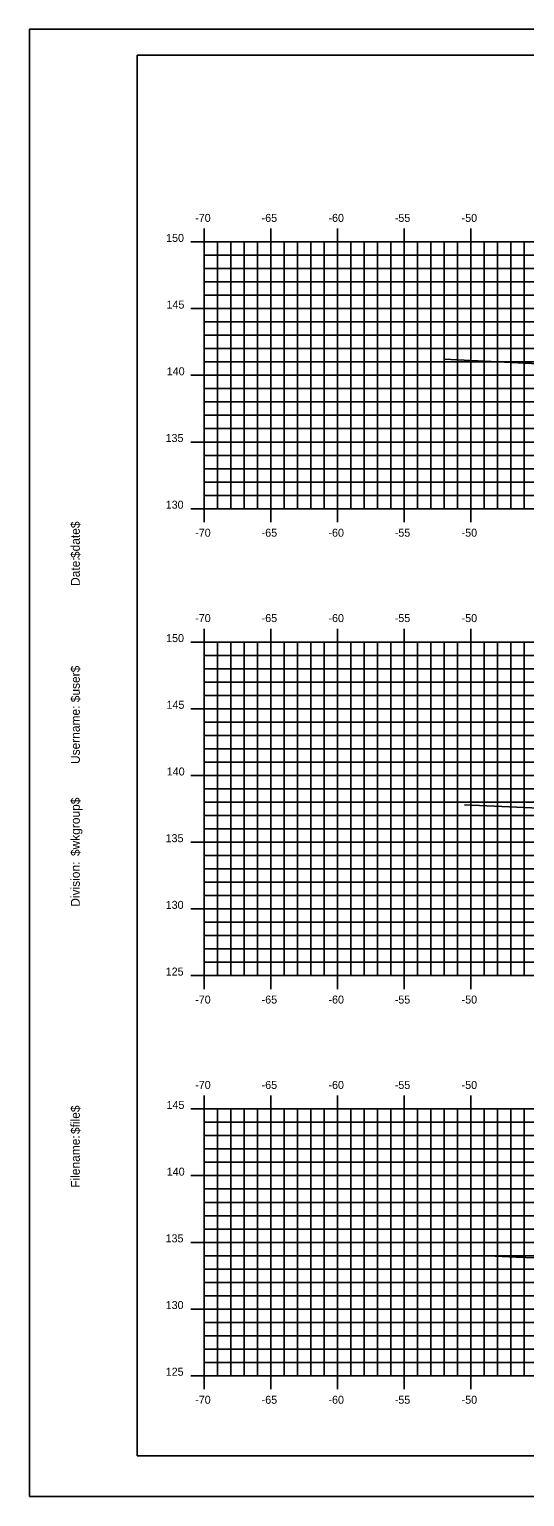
# Model space of a CAD drawing. Extents: x 1146525 to 1146695, y 608981 to 609091.
# Drawn here: x 1146524.6 to 1146561.7, y 608981.3 to 609091.3 of the extents above; entities that cross this region are included whole.
import ezdxf

# ---------------------------------------------------------------- set-up
doc = ezdxf.new("R2010")
doc.units = 0
for name, color, linetype in [('BORDER', 7, 'Continuous'), ('H_V ANNOTATION', 7, 'Continuous'), ('MAJOR', 7, 'Continuous'), ('MINOR', 7, 'Continuous'), ('PLOT BOUNDARY', 7, 'Continuous'), ('S_Roadway_Centerline', 7, 'Continuous')]:
    doc.layers.add(name, color=color, linetype=linetype)

msp = doc.modelspace()

# ---------------------------------------------------------------- linework, layer by layer
at = {"layer": 'BORDER'}
msp.add_lwpolyline([(1146532.67, 608984.34), (1146692.67, 608984.34), (1146692.67, 609089.34), (1146532.67, 609089.34)], close=True, dxfattribs=at)
at = {"layer": 'MAJOR'}
for p, q in [((1146537.67, 609076.34), (1146537.67, 609075.34)), ((1146542.67, 609076.34), (1146542.67, 609075.34)), ((1146547.67, 609076.34), (1146547.67, 609075.34)), ((1146552.67, 609076.34), (1146552.67, 609075.34)), ((1146557.67, 609076.34), (1146557.67, 609075.34)), ((1146536.67, 609075.34), (1146537.67, 609075.34)), ((1146537.67, 609075.34), (1146677.67, 609075.34)), ((1146537.67, 609055.34), (1146537.67, 609075.34)), ((1146537.67, 609055.34), (1146537.67, 609075.34)), ((1146537.67, 609075.34), (1146677.67, 609075.34)), ((1146542.67, 609055.34), (1146542.67, 609075.34)), ((1146547.67, 609055.34), (1146547.67, 609075.34)), ((1146552.67, 609055.34), (1146552.67, 609075.34)), ((1146557.67, 609055.34), (1146557.67, 609075.34)), ((1146536.67, 609070.34), (1146537.67, 609070.34)), ((1146537.67, 609070.34), (1146677.67, 609070.34)), ((1146536.67, 609065.34), (1146537.67, 609065.34)), ((1146537.67, 609065.34), (1146677.67, 609065.34)), ((1146536.67, 609060.34), (1146537.67, 609060.34)), ((1146537.67, 609060.34), (1146677.67, 609060.34)), ((1146536.67, 609055.34), (1146537.67, 609055.34)), ((1146537.67, 609055.34), (1146677.67, 609055.34)), ((1146537.67, 609055.34), (1146677.67, 609055.34)), ((1146537.67, 609054.33), (1146537.67, 609055.34)), ((1146542.67, 609054.33), (1146542.67, 609055.34)), ((1146547.67, 609054.33), (1146547.67, 609055.34)), ((1146552.67, 609054.33), (1146552.67, 609055.34)), ((1146557.67, 609054.33), (1146557.67, 609055.34)), ((1146537.67, 609046.34), (1146537.67, 609045.34)), ((1146542.67, 609046.34), (1146542.67, 609045.34)), ((1146547.67, 609046.34), (1146547.67, 609045.34)), ((1146552.67, 609046.34), (1146552.67, 609045.34)), ((1146557.67, 609046.34), (1146557.67, 609045.34)), ((1146536.67, 609045.34), (1146537.67, 609045.34)), ((1146537.67, 609045.34), (1146677.67, 609045.34)), ((1146537.67, 609020.34), (1146537.67, 609045.34)), ((1146537.67, 609020.34), (1146537.67, 609045.34)), ((1146537.67, 609045.34), (1146677.67, 609045.34)), ((1146542.67, 609020.34), (1146542.67, 609045.34)), ((1146547.67, 609020.34), (1146547.67, 609045.34)), ((1146552.67, 609020.34), (1146552.67, 609045.34)), ((1146557.67, 609020.34), (1146557.67, 609045.34)), ((1146536.67, 609040.34), (1146537.67, 609040.34)), ((1146537.67, 609040.34), (1146677.67, 609040.34)), ((1146536.67, 609035.34), (1146537.67, 609035.34)), ((1146537.67, 609035.34), (1146677.67, 609035.34)), ((1146536.67, 609030.34), (1146537.67, 609030.34)), ((1146537.67, 609030.34), (1146677.67, 609030.34)), ((1146536.67, 609025.34), (1146537.67, 609025.34)), ((1146537.67, 609025.34), (1146677.67, 609025.34)), ((1146536.67, 609020.34), (1146537.67, 609020.34)), ((1146537.67, 609020.34), (1146677.67, 609020.34)), ((1146537.67, 609020.34), (1146677.67, 609020.34)), ((1146537.67, 609019.33), (1146537.67, 609020.34)), ((1146542.67, 609019.33), (1146542.67, 609020.34)), ((1146547.67, 609019.33), (1146547.67, 609020.34)), ((1146552.67, 609019.33), (1146552.67, 609020.34)), ((1146557.67, 609019.33), (1146557.67, 609020.34)), ((1146537.67, 609011.34), (1146537.67, 609010.34)), ((1146542.67, 609011.34), (1146542.67, 609010.34)), ((1146547.67, 609011.34), (1146547.67, 609010.34)), ((1146552.67, 609011.34), (1146552.67, 609010.34)), ((1146557.67, 609011.34), (1146557.67, 609010.34)), ((1146536.67, 609010.34), (1146537.67, 609010.34)), ((1146537.67, 609010.34), (1146677.67, 609010.34)), ((1146537.67, 608990.34), (1146537.67, 609010.34)), ((1146537.67, 608990.34), (1146537.67, 609010.34)), ((1146537.67, 609010.34), (1146677.67, 609010.34)), ((1146542.67, 608990.34), (1146542.67, 609010.34)), ((1146547.67, 608990.34), (1146547.67, 609010.34)), ((1146552.67, 608990.34), (1146552.67, 609010.34)), ((1146557.67, 608990.34), (1146557.67, 609010.34)), ((1146536.67, 609005.34), (1146537.67, 609005.34)), ((1146537.67, 609005.34), (1146677.67, 609005.34)), ((1146536.67, 609000.34), (1146537.67, 609000.34)), ((1146537.67, 609000.34), (1146677.67, 609000.34)), ((1146536.67, 608995.34), (1146537.67, 608995.34)), ((1146537.67, 608995.34), (1146677.67, 608995.34)), ((1146536.67, 608990.34), (1146537.67, 608990.34)), ((1146537.67, 608990.34), (1146677.67, 608990.34)), ((1146537.67, 608990.34), (1146677.67, 608990.34)), ((1146537.67, 608989.33), (1146537.67, 608990.34)), ((1146542.67, 608989.33), (1146542.67, 608990.34)), ((1146547.67, 608989.33), (1146547.67, 608990.34)), ((1146552.67, 608989.33), (1146552.67, 608990.34)), ((1146557.67, 608989.33), (1146557.67, 608990.34))]:
    msp.add_line(p, q, dxfattribs=at)
at = {"layer": 'MINOR'}
for p, q in [((1146538.67, 609055.34), (1146538.67, 609075.34)), ((1146539.67, 609055.34), (1146539.67, 609075.34)), ((1146540.67, 609055.34), (1146540.67, 609075.34)), ((1146541.67, 609055.34), (1146541.67, 609075.34)), ((1146543.67, 609055.34), (1146543.67, 609075.34)), ((1146544.67, 609055.34), (1146544.67, 609075.34)), ((1146545.67, 609055.34), (1146545.67, 609075.34)), ((1146546.67, 609055.34), (1146546.67, 609075.34)), ((1146548.67, 609055.34), (1146548.67, 609075.34)), ((1146549.67, 609055.34), (1146549.67, 609075.34)), ((1146550.67, 609055.34), (1146550.67, 609075.34)), ((1146551.67, 609055.34), (1146551.67, 609075.34)), ((1146553.67, 609055.34), (1146553.67, 609075.34)), ((1146554.67, 609055.34), (1146554.67, 609075.34)), ((1146555.67, 609055.34), (1146555.67, 609075.34)), ((1146556.67, 609055.34), (1146556.67, 609075.34)), ((1146558.67, 609055.34), (1146558.67, 609075.34)), ((1146559.67, 609055.34), (1146559.67, 609075.34)), ((1146560.67, 609055.34), (1146560.67, 609075.34)), ((1146561.67, 609055.34), (1146561.67, 609075.34)), ((1146537.67, 609074.34), (1146677.67, 609074.34)), ((1146537.67, 609074.34), (1146538.67, 609074.34)), ((1146537.67, 609073.34), (1146677.67, 609073.34)), ((1146537.67, 609073.34), (1146538.67, 609073.34)), ((1146537.67, 609072.34), (1146677.67, 609072.34)), ((1146537.67, 609072.34), (1146538.67, 609072.34)), ((1146537.67, 609071.34), (1146677.67, 609071.34)), ((1146537.67, 609071.34), (1146538.67, 609071.34)), ((1146537.67, 609069.34), (1146677.67, 609069.34)), ((1146537.67, 609069.34), (1146538.67, 609069.34)), ((1146537.67, 609068.34), (1146677.67, 609068.34)), ((1146537.67, 609068.34), (1146538.67, 609068.34)), ((1146537.67, 609067.34), (1146677.67, 609067.34)), ((1146537.67, 609067.34), (1146538.67, 609067.34)), ((1146537.67, 609066.34), (1146677.67, 609066.34)), ((1146537.67, 609066.34), (1146538.67, 609066.34)), ((1146537.67, 609064.34), (1146677.67, 609064.34)), ((1146537.67, 609064.34), (1146538.67, 609064.34)), ((1146537.67, 609063.34), (1146677.67, 609063.34)), ((1146537.67, 609063.34), (1146538.67, 609063.34)), ((1146537.67, 609062.34), (1146677.67, 609062.34)), ((1146537.67, 609062.34), (1146538.67, 609062.34)), ((1146537.67, 609061.34), (1146677.67, 609061.34)), ((1146537.67, 609061.34), (1146538.67, 609061.34)), ((1146537.67, 609059.34), (1146677.67, 609059.34)), ((1146537.67, 609059.34), (1146538.67, 609059.34)), ((1146537.67, 609058.34), (1146677.67, 609058.34)), ((1146537.67, 609058.34), (1146538.67, 609058.34)), ((1146537.67, 609057.34), (1146677.67, 609057.34)), ((1146537.67, 609057.34), (1146538.67, 609057.34)), ((1146537.67, 609056.34), (1146677.67, 609056.34)), ((1146537.67, 609056.34), (1146538.67, 609056.34)), ((1146538.67, 609020.34), (1146538.67, 609045.34)), ((1146539.67, 609020.34), (1146539.67, 609045.34)), ((1146540.67, 609020.34), (1146540.67, 609045.34)), ((1146541.67, 609020.34), (1146541.67, 609045.34)), ((1146543.67, 609020.34), (1146543.67, 609045.34)), ((1146544.67, 609020.34), (1146544.67, 609045.34)), ((1146545.67, 609020.34), (1146545.67, 609045.34)), ((1146546.67, 609020.34), (1146546.67, 609045.34)), ((1146548.67, 609020.34), (1146548.67, 609045.34)), ((1146549.67, 609020.34), (1146549.67, 609045.34)), ((1146550.67, 609020.34), (1146550.67, 609045.34)), ((1146551.67, 609020.34), (1146551.67, 609045.34)), ((1146553.67, 609020.34), (1146553.67, 609045.34)), ((1146554.67, 609020.34), (1146554.67, 609045.34)), ((1146555.67, 609020.34), (1146555.67, 609045.34)), ((1146556.67, 609020.34), (1146556.67, 609045.34)), ((1146558.67, 609020.34), (1146558.67, 609045.34)), ((1146559.67, 609020.34), (1146559.67, 609045.34)), ((1146560.67, 609020.34), (1146560.67, 609045.34)), ((1146561.67, 609020.34), (1146561.67, 609045.34)), ((1146537.67, 609044.34), (1146677.67, 609044.34)), ((1146537.67, 609044.34), (1146538.67, 609044.34)), ((1146537.67, 609043.34), (1146677.67, 609043.34)), ((1146537.67, 609043.34), (1146538.67, 609043.34)), ((1146537.67, 609042.34), (1146677.67, 609042.34)), ((1146537.67, 609042.34), (1146538.67, 609042.34)), ((1146537.67, 609041.34), (1146677.67, 609041.34)), ((1146537.67, 609041.34), (1146538.67, 609041.34)), ((1146537.67, 609039.34), (1146677.67, 609039.34)), ((1146537.67, 609039.34), (1146538.67, 609039.34)), ((1146537.67, 609038.34), (1146677.67, 609038.34)), ((1146537.67, 609038.34), (1146538.67, 609038.34)), ((1146537.67, 609037.34), (1146677.67, 609037.34)), ((1146537.67, 609037.34), (1146538.67, 609037.34)), ((1146537.67, 609036.34), (1146677.67, 609036.34)), ((1146537.67, 609036.34), (1146538.67, 609036.34)), ((1146537.67, 609034.34), (1146677.67, 609034.34)), ((1146537.67, 609034.34), (1146538.67, 609034.34)), ((1146537.67, 609033.34), (1146677.67, 609033.34)), ((1146537.67, 609033.34), (1146538.67, 609033.34)), ((1146537.67, 609032.34), (1146677.67, 609032.34)), ((1146537.67, 609032.34), (1146538.67, 609032.34)), ((1146537.67, 609031.34), (1146677.67, 609031.34)), ((1146537.67, 609031.34), (1146538.67, 609031.34)), ((1146537.67, 609029.34), (1146677.67, 609029.34)), ((1146537.67, 609029.34), (1146538.67, 609029.34)), ((1146537.67, 609028.34), (1146677.67, 609028.34)), ((1146537.67, 609028.34), (1146538.67, 609028.34)), ((1146537.67, 609027.34), (1146677.67, 609027.34)), ((1146537.67, 609027.34), (1146538.67, 609027.34)), ((1146537.67, 609026.34), (1146677.67, 609026.34)), ((1146537.67, 609026.34), (1146538.67, 609026.34)), ((1146537.67, 609024.34), (1146677.67, 609024.34)), ((1146537.67, 609024.34), (1146538.67, 609024.34)), ((1146537.67, 609023.34), (1146677.67, 609023.34)), ((1146537.67, 609023.34), (1146538.67, 609023.34)), ((1146537.67, 609022.34), (1146677.67, 609022.34)), ((1146537.67, 609022.34), (1146538.67, 609022.34)), ((1146537.67, 609021.34), (1146677.67, 609021.34)), ((1146537.67, 609021.34), (1146538.67, 609021.34)), ((1146538.67, 608990.34), (1146538.67, 609010.34)), ((1146539.67, 608990.34), (1146539.67, 609010.34)), ((1146540.67, 608990.34), (1146540.67, 609010.34)), ((1146541.67, 608990.34), (1146541.67, 609010.34)), ((1146543.67, 608990.34), (1146543.67, 609010.34)), ((1146544.67, 608990.34), (1146544.67, 609010.34)), ((1146545.67, 608990.34), (1146545.67, 609010.34)), ((1146546.67, 608990.34), (1146546.67, 609010.34)), ((1146548.67, 608990.34), (1146548.67, 609010.34)), ((1146549.67, 608990.34), (1146549.67, 609010.34)), ((1146550.67, 608990.34), (1146550.67, 609010.34)), ((1146551.67, 608990.34), (1146551.67, 609010.34)), ((1146553.67, 608990.34), (1146553.67, 609010.34)), ((1146554.67, 608990.34), (1146554.67, 609010.34)), ((1146555.67, 608990.34), (1146555.67, 609010.34)), ((1146556.67, 608990.34), (1146556.67, 609010.34)), ((1146558.67, 608990.34), (1146558.67, 609010.34)), ((1146559.67, 608990.34), (1146559.67, 609010.34)), ((1146560.67, 608990.34), (1146560.67, 609010.34)), ((1146561.67, 608990.34), (1146561.67, 609010.34)), ((1146537.67, 609009.34), (1146677.67, 609009.34)), ((1146537.67, 609009.34), (1146538.67, 609009.34)), ((1146537.67, 609008.34), (1146677.67, 609008.34)), ((1146537.67, 609008.34), (1146538.67, 609008.34)), ((1146537.67, 609007.34), (1146677.67, 609007.34)), ((1146537.67, 609007.34), (1146538.67, 609007.34)), ((1146537.67, 609006.34), (1146677.67, 609006.34)), ((1146537.67, 609006.34), (1146538.67, 609006.34)), ((1146537.67, 609004.34), (1146677.67, 609004.34)), ((1146537.67, 609004.34), (1146538.67, 609004.34)), ((1146537.67, 609003.34), (1146677.67, 609003.34)), ((1146537.67, 609003.34), (1146538.67, 609003.34)), ((1146537.67, 609002.34), (1146677.67, 609002.34)), ((1146537.67, 609002.34), (1146538.67, 609002.34)), ((1146537.67, 609001.34), (1146677.67, 609001.34)), ((1146537.67, 609001.34), (1146538.67, 609001.34)), ((1146537.67, 608999.34), (1146677.67, 608999.34)), ((1146537.67, 608999.34), (1146538.67, 608999.34)), ((1146537.67, 608998.34), (1146677.67, 608998.34)), ((1146537.67, 608998.34), (1146538.67, 608998.34)), ((1146537.67, 608997.34), (1146677.67, 608997.34)), ((1146537.67, 608997.34), (1146538.67, 608997.34)), ((1146537.67, 608996.34), (1146677.67, 608996.34)), ((1146537.67, 608996.34), (1146538.67, 608996.34)), ((1146537.67, 608994.34), (1146677.67, 608994.34)), ((1146537.67, 608994.34), (1146538.67, 608994.34)), ((1146537.67, 608993.34), (1146677.67, 608993.34)), ((1146537.67, 608993.34), (1146538.67, 608993.34)), ((1146537.67, 608992.34), (1146677.67, 608992.34)), ((1146537.67, 608992.34), (1146538.67, 608992.34)), ((1146537.67, 608991.34), (1146677.67, 608991.34)), ((1146537.67, 608991.34), (1146538.67, 608991.34))]:
    msp.add_line(p, q, dxfattribs=at)
at = {"layer": 'PLOT BOUNDARY'}
msp.add_lwpolyline([(1146524.58, 608981.28), (1146694.58, 608981.28), (1146694.58, 609091.28), (1146524.58, 609091.28)], close=True, dxfattribs=at)
at = {"layer": 'S_Roadway_Centerline'}
for points in [[(1146555.66, 609066.54), (1146562.22, 609066.22), (1146582.41, 609065.07), (1146583.32, 609064.91), (1146587.85, 609063.5), (1146588.57, 609063.64), (1146593.36, 609064.95), (1146593.6, 609064.96), (1146595.56, 609064.97), (1146601.49, 609065.12), (1146606.93, 609065.19), (1146612.82, 609065.04), (1146617.66, 609064.93), (1146621.7, 609064.69), (1146621.82, 609064.68), (1146621.88, 609064.66), (1146624.76, 609063.49), (1146625.76, 609063.91), (1146635.49, 609067.85), (1146654.51, 609068.05), (1146655.61, 609068.02)], [(1146557.19, 609033.15), (1146565.05, 609032.78), (1146581.82, 609032.11), (1146584.31, 609031.66), (1146589.37, 609030.83), (1146592.03, 609031.48), (1146593.47, 609031.84), (1146594.03, 609031.88), (1146595.01, 609031.91), (1146600.28, 609032.09), (1146606.45, 609032.18), (1146612.28, 609032.04), (1146617.29, 609031.87), (1146619.52, 609031.64), (1146621.57, 609031.45), (1146622.76, 609030.93), (1146624.18, 609030.47), (1146629.55, 609032.75), (1146635.04, 609035.13), (1146648.1, 609035.72), (1146654.91, 609035.42)], [(1146558.97, 608999.32), (1146561.08, 608999.24), (1146581.4, 608998.53), (1146588.81, 608997.71), (1146588.86, 608997.7), (1146592.98, 608998.76), (1146592.99, 608998.76), (1146592.99, 608998.76), (1146594.91, 608998.76), (1146601.66, 608998.91), (1146606.09, 608999.07), (1146612.76, 608998.85), (1146617.1, 608998.7), (1146618.9, 608998.53), (1146621.3, 608998.36), (1146623.63, 608997.31), (1146624.92, 608996.89), (1146629.66, 608997.7), (1146630.24, 608997.88), (1146632.15, 608997.99), (1146654.81, 608998.74), (1146655.93, 608998.78), (1146656.09, 608998.78)]]:
    msp.add_lwpolyline(points, dxfattribs=at)

# ---------------------------------------------------------------- texts
at = {"layer": 'BORDER'}
for s, p in [('$date$', (1146528.36, 609051.64)), ('Date:', (1146528.36, 609049.55)), ('$user$', (1146528.36, 609040.83)), ('Username:', (1146528.36, 609036.2)), ('$wkgroup$', (1146528.36, 609029.3)), ('Division:', (1146528.36, 609025.5)), ('$file$', (1146528.36, 609008.46)), ('Filename:', (1146528.36, 609004.43))]:
    msp.add_text(s, height=0.67, rotation=90, dxfattribs=at).set_placement(p)
at = {"layer": 'H_V ANNOTATION'}
for s, p in [('-70', (1146537.01, 609076.84)), ('-65', (1146541.99, 609076.84)), ('-60', (1146547, 609076.84)), ('-55', (1146551.97, 609076.84)), ('-50', (1146556.98, 609076.84)), ('150', (1146534.83, 609075.34)), ('145', (1146534.86, 609070.34)), ('140', (1146534.88, 609065.34)), ('135', (1146534.79, 609060.34)), ('130', (1146534.8, 609055.34)), ('-70', (1146537.01, 609053.24)), ('-65', (1146541.99, 609053.24)), ('-60', (1146547, 609053.24)), ('-55', (1146551.97, 609053.24)), ('-50', (1146556.98, 609053.24)), ('-70', (1146537.01, 609046.84)), ('-65', (1146541.99, 609046.84)), ('-60', (1146547, 609046.84)), ('-55', (1146551.97, 609046.84)), ('-50', (1146556.98, 609046.84)), ('150', (1146534.83, 609045.34)), ('145', (1146534.86, 609040.34)), ('140', (1146534.88, 609035.34)), ('135', (1146534.79, 609030.34)), ('130', (1146534.8, 609025.34)), ('125', (1146534.8, 609020.34)), ('-70', (1146537.01, 609018.24)), ('-65', (1146541.99, 609018.24)), ('-60', (1146547, 609018.24)), ('-55', (1146551.97, 609018.24)), ('-50', (1146556.98, 609018.24)), ('-70', (1146537.01, 609011.84)), ('-65', (1146541.99, 609011.84)), ('-60', (1146547, 609011.84)), ('-55', (1146551.97, 609011.84)), ('-50', (1146556.98, 609011.84)), ('145', (1146534.86, 609010.34)), ('140', (1146534.88, 609005.34)), ('135', (1146534.79, 609000.34)), ('130', (1146534.8, 608995.34)), ('125', (1146534.8, 608990.34)), ('-70', (1146537.01, 608988.24)), ('-65', (1146541.99, 608988.24)), ('-60', (1146547, 608988.24)), ('-55', (1146551.97, 608988.24)), ('-50', (1146556.98, 608988.24))]:
    msp.add_text(s, height=0.6, dxfattribs=at).set_placement(p)
at = {"layer": 'MAJOR'}
for p in [(1146537.67, 609055.34), (1146537.67, 609020.34), (1146537.67, 608990.34)]:
    msp.add_text('-', height=0.006, dxfattribs=at).set_placement(p)

doc.saveas('drawing.dxf')
